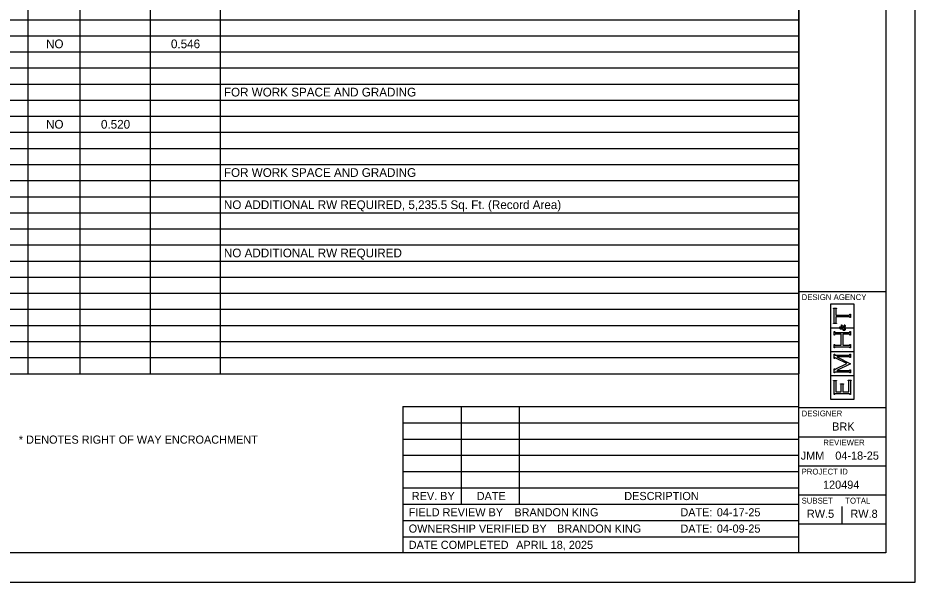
# Model space of a CAD drawing. Extents: x 0 to 34, y 0 to 22.
# Drawn here: x 18.58 to 34, y 0 to 9.7 of the extents above; entities that cross this region are included whole.
import ezdxf

# ---------------------------------------------------------------- set-up
doc = ezdxf.new("R2010")
doc.units = 0
for name, color, linetype in [('SH_Border', 7, 'Continuous'), ('SH_Cut_Line', 7, 'Continuous'), ('SH_Data', 7, 'Continuous'), ('SH_Text', 7, 'Continuous')]:
    doc.layers.add(name, color=color, linetype=linetype)

msp = doc.modelspace()

# ---------------------------------------------------------------- linework, layer by layer
at = {"layer": 'SH_Border'}
for p, q in [((32, 0.5), (32, 21.5)), ((32, 5), (33.5, 5)), ((32, 3), (33.5, 3)), ((32, 2.5), (33.5, 2.5)), ((32, 2), (33.5, 2)), ((32, 1.5), (33.5, 1.5)), ((32, 1), (33.5, 1))]:
    msp.add_line(p, q, dxfattribs=at)
msp.add_lwpolyline([(1.5, 21.5), (33.5, 21.5), (33.5, 0.5), (1.5, 0.5)], close=True, dxfattribs=at)
at = {"layer": 'SH_Cut_Line'}
msp.add_lwpolyline([(0, 0), (34, 0), (34, 22), (0, 22)], close=True, dxfattribs=at)
at = {"layer": 'SH_Data'}
for p, q in [((32.952, 4.779), (32.547, 4.779)), ((32.547, 4.779), (32.547, 4.375)), ((32.598, 4.704), (32.598, 4.711)), ((32.598, 4.711), (32.65, 4.711)), ((32.603, 4.703), (32.598, 4.704)), ((32.606, 4.701), (32.603, 4.703)), ((32.608, 4.699), (32.606, 4.701)), ((32.61, 4.696), (32.608, 4.699)), ((32.611, 4.692), (32.61, 4.696)), ((32.611, 4.687), (32.611, 4.692)), ((32.611, 4.468), (32.611, 4.687)), ((32.638, 4.696), (32.637, 4.692)), ((32.637, 4.692), (32.637, 4.687)), ((32.637, 4.687), (32.637, 4.593)), ((32.64, 4.699), (32.638, 4.696)), ((32.642, 4.701), (32.64, 4.699)), ((32.645, 4.703), (32.642, 4.701)), ((32.65, 4.704), (32.645, 4.703)), ((32.65, 4.711), (32.65, 4.704)), ((32.952, 4.375), (32.952, 4.779)), ((32.637, 4.593), (32.864, 4.593)), ((32.864, 4.561), (32.637, 4.561)), ((32.637, 4.561), (32.637, 4.468)), ((32.864, 4.593), (32.869, 4.593)), ((32.87, 4.561), (32.864, 4.561)), ((32.869, 4.593), (32.873, 4.594)), ((32.874, 4.56), (32.87, 4.561)), ((32.873, 4.594), (32.876, 4.596)), ((32.876, 4.559), (32.874, 4.56)), ((32.876, 4.596), (32.878, 4.597)), ((32.878, 4.557), (32.876, 4.559)), ((32.878, 4.597), (32.88, 4.601)), ((32.88, 4.553), (32.878, 4.557)), ((32.88, 4.601), (32.881, 4.606)), ((32.881, 4.548), (32.88, 4.553)), ((32.881, 4.606), (32.888, 4.606)), ((32.888, 4.548), (32.881, 4.548)), ((32.888, 4.606), (32.888, 4.548)), ((32.547, 4.375), (32.696, 4.375)), ((32.696, 4.369), (32.547, 4.369)), ((32.547, 4.369), (32.547, 3.965)), ((32.598, 4.45), (32.603, 4.451)), ((32.598, 4.444), (32.598, 4.45)), ((32.65, 4.444), (32.598, 4.444)), ((32.603, 4.451), (32.606, 4.453)), ((32.606, 4.453), (32.608, 4.455)), ((32.608, 4.455), (32.61, 4.458)), ((32.61, 4.458), (32.611, 4.462)), ((32.611, 4.462), (32.611, 4.468)), ((32.637, 4.468), (32.637, 4.462)), ((32.637, 4.462), (32.638, 4.458)), ((32.638, 4.458), (32.64, 4.455)), ((32.64, 4.455), (32.642, 4.453)), ((32.642, 4.453), (32.645, 4.451)), ((32.645, 4.451), (32.65, 4.45)), ((32.65, 4.45), (32.65, 4.444)), ((32.696, 4.375), (32.696, 4.369)), ((32.703, 4.379), (32.705, 4.383)), ((32.703, 4.373), (32.703, 4.379)), ((32.703, 4.368), (32.703, 4.373)), ((32.705, 4.363), (32.703, 4.368)), ((32.705, 4.383), (32.708, 4.387)), ((32.708, 4.358), (32.705, 4.363)), ((32.708, 4.387), (32.711, 4.39)), ((32.709, 4.379), (32.708, 4.376)), ((32.708, 4.376), (32.708, 4.373)), ((32.708, 4.373), (32.708, 4.369)), ((32.708, 4.369), (32.71, 4.366)), ((32.712, 4.353), (32.708, 4.358)), ((32.712, 4.381), (32.709, 4.379)), ((32.71, 4.366), (32.712, 4.364)), ((32.711, 4.39), (32.715, 4.392)), ((32.714, 4.383), (32.712, 4.381)), ((32.712, 4.364), (32.715, 4.362)), ((32.718, 4.35), (32.712, 4.353)), ((32.716, 4.384), (32.714, 4.383)), ((32.715, 4.392), (32.72, 4.392)), ((32.715, 4.362), (32.718, 4.361)), ((32.72, 4.384), (32.716, 4.384)), ((32.718, 4.361), (32.721, 4.361)), ((32.726, 4.35), (32.718, 4.35)), ((32.72, 4.392), (32.725, 4.392)), ((32.724, 4.384), (32.72, 4.384)), ((32.721, 4.361), (32.723, 4.361)), ((32.723, 4.361), (32.725, 4.362)), ((32.728, 4.382), (32.724, 4.384)), ((32.725, 4.392), (32.729, 4.39)), ((32.725, 4.362), (32.728, 4.362)), ((32.729, 4.35), (32.726, 4.35)), ((32.731, 4.38), (32.728, 4.382)), ((32.728, 4.362), (32.731, 4.363)), ((32.729, 4.39), (32.732, 4.387)), ((32.731, 4.35), (32.729, 4.35)), ((32.734, 4.377), (32.731, 4.38)), ((32.731, 4.363), (32.735, 4.365)), ((32.734, 4.351), (32.731, 4.35)), ((32.732, 4.387), (32.736, 4.383)), ((32.737, 4.372), (32.734, 4.377)), ((32.737, 4.352), (32.734, 4.351)), ((32.735, 4.365), (32.74, 4.367)), ((32.736, 4.383), (32.74, 4.378)), ((32.74, 4.367), (32.737, 4.372)), ((32.741, 4.353), (32.737, 4.352)), ((32.738, 4.393), (32.738, 4.422)), ((32.738, 4.422), (32.741, 4.422)), ((32.741, 4.393), (32.738, 4.393)), ((32.74, 4.378), (32.744, 4.369)), ((32.741, 4.422), (32.741, 4.418)), ((32.741, 4.418), (32.742, 4.415)), ((32.742, 4.396), (32.741, 4.395)), ((32.741, 4.395), (32.741, 4.393)), ((32.746, 4.355), (32.741, 4.353)), ((32.742, 4.415), (32.743, 4.413)), ((32.743, 4.397), (32.742, 4.396)), ((32.743, 4.413), (32.745, 4.411)), ((32.745, 4.399), (32.743, 4.397)), ((32.744, 4.369), (32.754, 4.375)), ((32.745, 4.411), (32.749, 4.408)), ((32.746, 4.399), (32.745, 4.399)), ((32.748, 4.399), (32.746, 4.399)), ((32.752, 4.344), (32.746, 4.355)), ((32.755, 4.399), (32.748, 4.399)), ((32.749, 4.408), (32.756, 4.404)), ((32.756, 4.36), (32.751, 4.357)), ((32.751, 4.357), (32.754, 4.352)), ((32.757, 4.337), (32.752, 4.344)), ((32.754, 4.375), (32.764, 4.381)), ((32.754, 4.352), (32.757, 4.348)), ((32.763, 4.395), (32.755, 4.399)), ((32.756, 4.404), (32.763, 4.4)), ((32.761, 4.363), (32.756, 4.36)), ((32.757, 4.348), (32.761, 4.345)), ((32.763, 4.333), (32.757, 4.337)), ((32.764, 4.365), (32.761, 4.363)), ((32.761, 4.345), (32.765, 4.343)), ((32.763, 4.4), (32.77, 4.396)), ((32.772, 4.387), (32.763, 4.395)), ((32.768, 4.329), (32.763, 4.333)), ((32.764, 4.381), (32.772, 4.387)), ((32.768, 4.367), (32.764, 4.365)), ((32.765, 4.343), (32.769, 4.341)), ((32.774, 4.372), (32.768, 4.367)), ((32.774, 4.327), (32.768, 4.329)), ((32.769, 4.341), (32.773, 4.341)), ((32.77, 4.396), (32.776, 4.391)), ((32.773, 4.341), (32.778, 4.341)), ((32.782, 4.378), (32.774, 4.372)), ((32.779, 4.327), (32.774, 4.327)), ((32.776, 4.391), (32.781, 4.395)), ((32.778, 4.341), (32.782, 4.343)), ((32.779, 4.423), (32.781, 4.426)), ((32.782, 4.422), (32.779, 4.423)), ((32.785, 4.327), (32.779, 4.327)), ((32.781, 4.426), (32.787, 4.424)), ((32.781, 4.395), (32.784, 4.398)), ((32.785, 4.421), (32.782, 4.422)), ((32.786, 4.373), (32.782, 4.378)), ((32.782, 4.343), (32.786, 4.346)), ((32.784, 4.398), (32.786, 4.401)), ((32.786, 4.419), (32.785, 4.421)), ((32.79, 4.329), (32.785, 4.327)), ((32.788, 4.417), (32.786, 4.419)), ((32.786, 4.401), (32.788, 4.404)), ((32.791, 4.386), (32.786, 4.381)), ((32.786, 4.381), (32.791, 4.376)), ((32.788, 4.369), (32.786, 4.373)), ((32.786, 4.346), (32.789, 4.349)), ((32.787, 4.424), (32.792, 4.421)), ((32.789, 4.414), (32.788, 4.417)), ((32.788, 4.404), (32.789, 4.408)), ((32.79, 4.367), (32.788, 4.369)), ((32.789, 4.411), (32.789, 4.414)), ((32.789, 4.408), (32.789, 4.411)), ((32.789, 4.349), (32.791, 4.353)), ((32.791, 4.364), (32.79, 4.367)), ((32.793, 4.334), (32.79, 4.329)), ((32.794, 4.39), (32.791, 4.386)), ((32.791, 4.376), (32.795, 4.37)), ((32.791, 4.361), (32.791, 4.364)), ((32.791, 4.359), (32.791, 4.361)), ((32.791, 4.353), (32.791, 4.359)), ((32.792, 4.421), (32.795, 4.418)), ((32.797, 4.338), (32.793, 4.334)), ((32.796, 4.394), (32.794, 4.39)), ((32.795, 4.418), (32.798, 4.414)), ((32.795, 4.37), (32.797, 4.366)), ((32.798, 4.397), (32.796, 4.394)), ((32.797, 4.366), (32.798, 4.361)), ((32.799, 4.344), (32.797, 4.338)), ((32.798, 4.414), (32.799, 4.41)), ((32.799, 4.401), (32.798, 4.397)), ((32.798, 4.361), (32.799, 4.357)), ((32.799, 4.41), (32.799, 4.405)), ((32.799, 4.405), (32.799, 4.401)), ((32.803, 4.369), (32.799, 4.375)), ((32.799, 4.375), (32.952, 4.375)), ((32.799, 4.357), (32.799, 4.352)), ((32.799, 4.352), (32.799, 4.344)), ((32.952, 4.369), (32.803, 4.369)), ((32.952, 3.965), (32.952, 4.369)), ((32.611, 4.249), (32.611, 4.307)), ((32.611, 4.307), (32.617, 4.307)), ((32.617, 4.249), (32.611, 4.249)), ((32.617, 4.307), (32.619, 4.302)), ((32.618, 4.254), (32.617, 4.249)), ((32.62, 4.258), (32.618, 4.254)), ((32.619, 4.302), (32.62, 4.298)), ((32.62, 4.298), (32.623, 4.297)), ((32.623, 4.26), (32.62, 4.258)), ((32.623, 4.297), (32.625, 4.295)), ((32.625, 4.261), (32.623, 4.26)), ((32.625, 4.295), (32.629, 4.294)), ((32.629, 4.262), (32.625, 4.261)), ((32.629, 4.294), (32.635, 4.294)), ((32.635, 4.262), (32.629, 4.262)), ((32.635, 4.294), (32.864, 4.294)), ((32.732, 4.262), (32.635, 4.262)), ((32.732, 4.072), (32.732, 4.262)), ((32.864, 4.262), (32.759, 4.262)), ((32.759, 4.262), (32.759, 4.072)), ((32.864, 4.294), (32.869, 4.294)), ((32.87, 4.262), (32.864, 4.262)), ((32.869, 4.294), (32.873, 4.295)), ((32.874, 4.261), (32.87, 4.262)), ((32.873, 4.295), (32.876, 4.297)), ((32.876, 4.26), (32.874, 4.261)), ((32.876, 4.297), (32.878, 4.298)), ((32.878, 4.258), (32.876, 4.26)), ((32.878, 4.298), (32.88, 4.302)), ((32.88, 4.254), (32.878, 4.258)), ((32.88, 4.302), (32.881, 4.307)), ((32.881, 4.249), (32.88, 4.254)), ((32.881, 4.307), (32.888, 4.307)), ((32.888, 4.249), (32.881, 4.249)), ((32.888, 4.307), (32.888, 4.249)), ((32.611, 4.027), (32.611, 4.085)), ((32.611, 4.085), (32.617, 4.085)), ((32.617, 4.027), (32.611, 4.027)), ((32.617, 4.085), (32.619, 4.08)), ((32.618, 4.032), (32.617, 4.027)), ((32.62, 4.036), (32.618, 4.032)), ((32.619, 4.08), (32.62, 4.076)), ((32.62, 4.076), (32.623, 4.074)), ((32.623, 4.037), (32.62, 4.036)), ((32.623, 4.074), (32.625, 4.073)), ((32.625, 4.039), (32.623, 4.037)), ((32.625, 4.073), (32.629, 4.072)), ((32.629, 4.04), (32.625, 4.039)), ((32.629, 4.072), (32.635, 4.072)), ((32.635, 4.04), (32.629, 4.04)), ((32.635, 4.072), (32.732, 4.072)), ((32.864, 4.04), (32.635, 4.04)), ((32.759, 4.072), (32.864, 4.072)), ((32.864, 4.072), (32.87, 4.072)), ((32.87, 4.04), (32.864, 4.04)), ((32.87, 4.072), (32.874, 4.073)), ((32.874, 4.039), (32.87, 4.04)), ((32.874, 4.073), (32.876, 4.074)), ((32.876, 4.038), (32.874, 4.039)), ((32.876, 4.074), (32.878, 4.076)), ((32.878, 4.036), (32.876, 4.038)), ((32.878, 4.076), (32.88, 4.08)), ((32.88, 4.032), (32.878, 4.036)), ((32.88, 4.08), (32.881, 4.085)), ((32.881, 4.027), (32.88, 4.032)), ((32.881, 4.085), (32.888, 4.085)), ((32.888, 4.027), (32.881, 4.027)), ((32.888, 4.085), (32.888, 4.027)), ((32.547, 3.965), (32.952, 3.965)), ((32.952, 3.959), (32.547, 3.959)), ((32.547, 3.959), (32.547, 3.555)), ((32.611, 3.845), (32.611, 3.918)), ((32.611, 3.918), (32.617, 3.918)), ((32.617, 3.918), (32.619, 3.912)), ((32.619, 3.912), (32.62, 3.909)), ((32.62, 3.909), (32.623, 3.907)), ((32.622, 3.855), (32.62, 3.852)), ((32.626, 3.855), (32.622, 3.855)), ((32.623, 3.907), (32.625, 3.905)), ((32.625, 3.905), (32.629, 3.905)), ((32.629, 3.855), (32.626, 3.855)), ((32.629, 3.905), (32.635, 3.905)), ((32.633, 3.853), (32.629, 3.855)), ((32.635, 3.905), (32.864, 3.905)), ((32.864, 3.873), (32.654, 3.873)), ((32.654, 3.873), (32.888, 3.755)), ((32.75, 4), (32.75, 4)), ((32.864, 3.905), (32.869, 3.905)), ((32.87, 3.873), (32.864, 3.873)), ((32.869, 3.905), (32.873, 3.905)), ((32.874, 3.872), (32.87, 3.873)), ((32.873, 3.905), (32.876, 3.907)), ((32.876, 3.87), (32.874, 3.872)), ((32.876, 3.907), (32.878, 3.909)), ((32.878, 3.869), (32.876, 3.87)), ((32.878, 3.909), (32.88, 3.912)), ((32.88, 3.865), (32.878, 3.869)), ((32.88, 3.912), (32.881, 3.918)), ((32.881, 3.86), (32.88, 3.865)), ((32.881, 3.918), (32.888, 3.918)), ((32.888, 3.86), (32.881, 3.86)), ((32.888, 3.918), (32.888, 3.86)), ((32.952, 3.555), (32.952, 3.959)), ((32.617, 3.845), (32.611, 3.845)), ((32.62, 3.852), (32.617, 3.845)), ((32.64, 3.85), (32.633, 3.853)), ((32.825, 3.757), (32.64, 3.85)), ((32.641, 3.665), (32.825, 3.757)), ((32.888, 3.755), (32.654, 3.638)), ((32.547, 3.555), (32.952, 3.555)), ((32.952, 3.549), (32.547, 3.549)), ((32.547, 3.549), (32.547, 3.145)), ((32.611, 3.596), (32.611, 3.668)), ((32.611, 3.668), (32.617, 3.668)), ((32.617, 3.596), (32.611, 3.596)), ((32.617, 3.668), (32.62, 3.662)), ((32.618, 3.602), (32.617, 3.596)), ((32.62, 3.605), (32.618, 3.602)), ((32.62, 3.662), (32.622, 3.658)), ((32.623, 3.607), (32.62, 3.605)), ((32.622, 3.658), (32.626, 3.658)), ((32.625, 3.609), (32.623, 3.607)), ((32.629, 3.609), (32.625, 3.609)), ((32.626, 3.658), (32.627, 3.658)), ((32.627, 3.658), (32.633, 3.661)), ((32.635, 3.609), (32.629, 3.609)), ((32.633, 3.661), (32.641, 3.665)), ((32.864, 3.609), (32.635, 3.609)), ((32.654, 3.638), (32.864, 3.638)), ((32.864, 3.638), (32.869, 3.638)), ((32.87, 3.609), (32.864, 3.609)), ((32.869, 3.638), (32.873, 3.639)), ((32.874, 3.609), (32.87, 3.609)), ((32.873, 3.639), (32.876, 3.641)), ((32.876, 3.607), (32.874, 3.609)), ((32.876, 3.641), (32.878, 3.643)), ((32.878, 3.605), (32.876, 3.607)), ((32.878, 3.643), (32.88, 3.646)), ((32.88, 3.602), (32.878, 3.605)), ((32.88, 3.646), (32.881, 3.651)), ((32.881, 3.596), (32.88, 3.602)), ((32.881, 3.651), (32.888, 3.651)), ((32.888, 3.596), (32.881, 3.596)), ((32.888, 3.651), (32.888, 3.596)), ((32.952, 3.145), (32.952, 3.549)), ((32.598, 3.462), (32.598, 3.469)), ((32.598, 3.469), (32.65, 3.469)), ((32.603, 3.461), (32.598, 3.462)), ((32.606, 3.459), (32.603, 3.461)), ((32.608, 3.457), (32.606, 3.459)), ((32.61, 3.455), (32.608, 3.457)), ((32.611, 3.451), (32.61, 3.455)), ((32.611, 3.445), (32.611, 3.451)), ((32.611, 3.225), (32.611, 3.445)), ((32.64, 3.457), (32.638, 3.455)), ((32.638, 3.455), (32.638, 3.451)), ((32.638, 3.451), (32.638, 3.445)), ((32.638, 3.445), (32.638, 3.27)), ((32.642, 3.459), (32.64, 3.457)), ((32.645, 3.461), (32.642, 3.459)), ((32.65, 3.462), (32.645, 3.461)), ((32.65, 3.469), (32.65, 3.462)), ((32.719, 3.402), (32.719, 3.408)), ((32.719, 3.408), (32.772, 3.408)), ((32.724, 3.401), (32.719, 3.402)), ((32.728, 3.399), (32.724, 3.401)), ((32.729, 3.396), (32.728, 3.399)), ((32.731, 3.394), (32.729, 3.396)), ((32.732, 3.39), (32.731, 3.394)), ((32.76, 3.394), (32.759, 3.39)), ((32.761, 3.396), (32.76, 3.394)), ((32.763, 3.399), (32.761, 3.396)), ((32.767, 3.401), (32.763, 3.399)), ((32.772, 3.402), (32.767, 3.401)), ((32.772, 3.408), (32.772, 3.402)), ((32.848, 3.465), (32.848, 3.472)), ((32.848, 3.472), (32.901, 3.472)), ((32.853, 3.464), (32.848, 3.465)), ((32.857, 3.462), (32.853, 3.464)), ((32.859, 3.46), (32.857, 3.462)), ((32.86, 3.458), (32.859, 3.46)), ((32.861, 3.453), (32.86, 3.458)), ((32.861, 3.448), (32.861, 3.453)), ((32.861, 3.27), (32.861, 3.448)), ((32.889, 3.457), (32.888, 3.453)), ((32.888, 3.453), (32.888, 3.448)), ((32.888, 3.448), (32.888, 3.225)), ((32.891, 3.46), (32.889, 3.457)), ((32.892, 3.462), (32.891, 3.46)), ((32.896, 3.464), (32.892, 3.462)), ((32.901, 3.465), (32.896, 3.464)), ((32.901, 3.472), (32.901, 3.465)), ((32.629, 3.238), (32.625, 3.237)), ((32.635, 3.238), (32.629, 3.238)), ((32.864, 3.238), (32.635, 3.238)), ((32.638, 3.27), (32.732, 3.27)), ((32.732, 3.384), (32.732, 3.39)), ((32.732, 3.27), (32.732, 3.384)), ((32.759, 3.39), (32.759, 3.384)), ((32.759, 3.384), (32.759, 3.27)), ((32.759, 3.27), (32.861, 3.27)), ((32.87, 3.238), (32.864, 3.238)), ((32.874, 3.237), (32.87, 3.238)), ((32.547, 3.145), (32.952, 3.145)), ((32.617, 3.225), (32.611, 3.225)), ((32.619, 3.23), (32.617, 3.225)), ((32.62, 3.234), (32.619, 3.23)), ((32.623, 3.235), (32.62, 3.234)), ((32.625, 3.237), (32.623, 3.235)), ((32.876, 3.235), (32.874, 3.237)), ((32.878, 3.234), (32.876, 3.235)), ((32.88, 3.23), (32.878, 3.234)), ((32.881, 3.225), (32.88, 3.23)), ((32.888, 3.225), (32.881, 3.225)), ((32.75, 1), (32.75, 1.3))]:
    msp.add_line(p, q, dxfattribs=at)
at = {"layer": 'SH_Text'}
for p, q in [((18.752, 19.957), (18.752, 3.584)), ((19.647, 19.957), (19.647, 3.584)), ((22.056, 19.957), (22.056, 3.584)), ((32, 19.957), (32, 3.584)), ((20.851, 14.928), (20.851, 3.584)), ((1.5, 9.671), (32, 9.671)), ((1.5, 9.395), (32, 9.395)), ((1.5, 9.118), (32, 9.118)), ((1.5, 8.841), (32, 8.841)), ((1.5, 8.565), (32, 8.565)), ((1.5, 8.288), (32, 8.288)), ((1.5, 8.011), (32, 8.011)), ((1.5, 7.735), (32, 7.735)), ((1.5, 7.458), (32, 7.458)), ((1.5, 7.181), (32, 7.181)), ((1.5, 6.905), (32, 6.905)), ((1.5, 6.628), (32, 6.628)), ((1.5, 6.351), (32, 6.351)), ((1.5, 6.074), (32, 6.074)), ((1.5, 5.798), (32, 5.798)), ((1.5, 5.521), (32, 5.521)), ((1.5, 5.244), (32, 5.244)), ((1.5, 4.968), (32, 4.968)), ((1.5, 4.691), (32, 4.691)), ((1.5, 4.414), (32, 4.414)), ((1.5, 4.138), (32, 4.138)), ((1.5, 3.861), (32, 3.861)), ((1.5, 3.584), (32, 3.584)), ((25.197, 3.02), (25.197, 0.5)), ((25.197, 3.02), (32, 3.02)), ((26.197, 3.02), (26.197, 1.34)), ((27.197, 3.02), (27.197, 1.34)), ((25.197, 2.74), (32, 2.74)), ((25.197, 2.46), (32, 2.46)), ((25.197, 2.18), (32, 2.18)), ((25.197, 1.9), (32, 1.9)), ((25.197, 1.62), (32, 1.62)), ((25.197, 1.34), (32, 1.34)), ((25.197, 1.06), (32, 1.06)), ((25.197, 0.78), (32, 0.78)), ((32, 0.5), (32, 0.5))]:
    msp.add_line(p, q, dxfattribs=at)

# ---------------------------------------------------------------- texts
at = {"layer": 'SH_Data'}
for s, height, p in [('DESIGN AGENCY', 0.1, (32.05, 4.85)), ('DESIGNER', 0.1, (32.05, 2.85)), ('BRK', 0.14, (32.575, 2.605)), ('REVIEWER', 0.1, (32.422, 2.35)), ('JMM', 0.14, (32.035, 2.105)), ('04-18-25', 0.14, (32.629, 2.105)), ('PROJECT ID', 0.1, (32.05, 1.85)), ('SUBSET', 0.1, (32.05, 1.35)), ('TOTAL', 0.1, (32.8, 1.35)), ('RW.5', 0.14, (32.141, 1.105)), ('RW.8', 0.14, (32.889, 1.105))]:
    msp.add_text(s, height=height, dxfattribs=at).set_placement(p)
at = {"layer": 'SH_Text'}
for s, height, p in [('NO', 0.1497, (19.064, 9.181)), ('0.546', 0.1497, (21.211, 9.181)), ('FOR WORK SPACE AND GRADING', 0.14973, (22.121, 8.351)), ('NO', 0.1497, (19.064, 7.798)), ('0.520', 0.1497, (20.008, 7.798)), ('FOR WORK SPACE AND GRADING', 0.14973, (22.121, 6.968)), ('NO ADDITIONAL RW REQUIRED, 5,235.5 Sq. Ft. (Record Area)', 0.14973, (22.121, 6.415)), ('NO ADDITIONAL RW REQUIRED', 0.14973, (22.121, 5.585)), ('* DENOTES RIGHT OF WAY ENCROACHMENT', 0.14, (18.596, 2.38)), ('120494', 0.14, (32.418, 1.605)), ('REV. BY', 0.14, (25.35, 1.41)), ('DATE', 0.14, (26.466, 1.41)), ('DESCRIPTION', 0.14, (29.002, 1.41)), ('FIELD REVIEW BY', 0.14, (25.297, 1.13)), ('BRANDON KING', 0.14, (27.113, 1.13)), ('DATE:', 0.14, (29.967, 1.13)), ('04-17-25', 0.14, (30.593, 1.13)), ('OWNERSHIP VERIFIED BY', 0.14, (25.297, 0.85)), ('BRANDON KING', 0.14, (27.848, 0.85)), ('DATE:', 0.14, (29.967, 0.85)), ('04-09-25', 0.14, (30.593, 0.85)), ('DATE COMPLETED', 0.14, (25.297, 0.57)), ('APRIL 18, 2025', 0.14, (27.144, 0.57))]:
    msp.add_text(s, height=height, dxfattribs=at).set_placement(p)

doc.saveas('drawing.dxf')
